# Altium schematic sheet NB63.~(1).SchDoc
size 279 x 215 mm
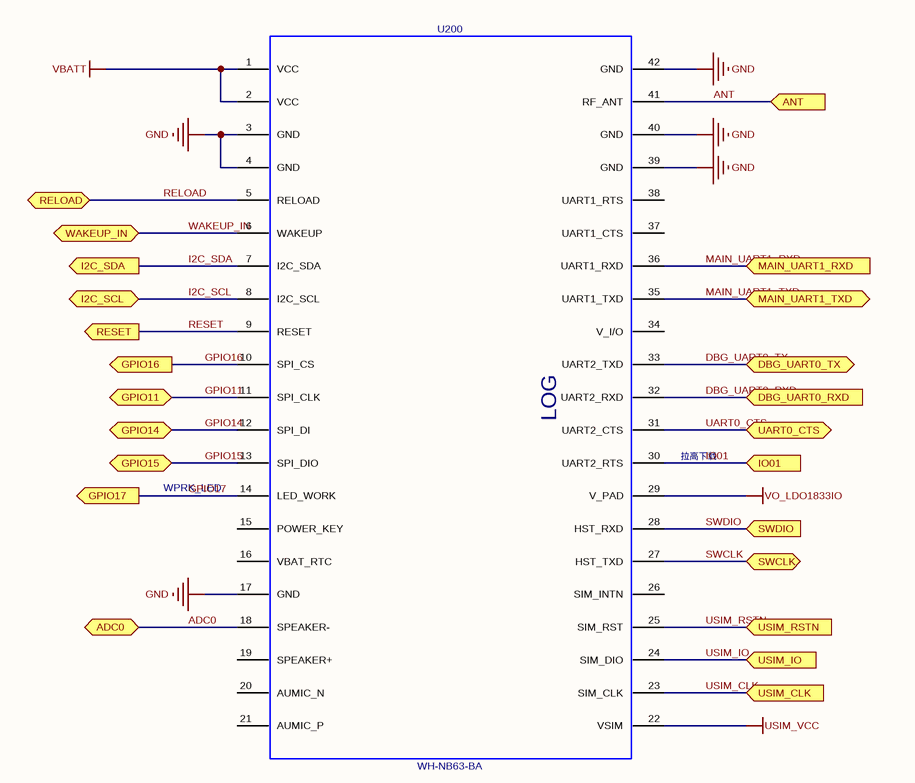
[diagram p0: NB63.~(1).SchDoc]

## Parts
U200  WH-NB63-BA  [NB63-I/O]

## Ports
ADC0 (bidir), ANT, DBG_UART0_RXD (in), DBG_UART0_TX (bidir), GPIO11 (bidir), GPIO14 (bidir), GPIO15 (bidir), GPIO16 (out), GPIO17 (out), I2C_SCL (bidir), I2C_SDA (out), IO01 (in), MAIN_UART1_RXD (in), MAIN_UART1_TXD (bidir), RELOAD (bidir), RESET (out), SWCLK (bidir), SWDIO (in), UART0_CTS (bidir), USIM_CLK (in), USIM_IO (in), USIM_RSTN (in), WAKEUP_IN (bidir)

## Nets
GND: U200.3(GND) U200.4(GND) U200.17(GND) U200.39(GND) U200.40(GND) U200.42(GND)
USIM_VCC: U200.22(VSIM)
VBATT: U200.1(VCC) U200.2(VCC)
VO_LDO1833IO: U200.29(V_PAD)
ADC0: U200.18(SPEAKER-) ; port ADC0
ANT: U200.41(RF_ANT) ; port ANT
DBG_UART0_RXD: U200.32(UART2_RXD) ; port DBG_UART0_RXD
DBG_UART0_TX: U200.33(UART2_TXD) ; port DBG_UART0_TX
GPIO11: U200.11(SPI_CLK) ; port GPIO11
GPIO14: U200.12(SPI_DI) ; port GPIO14
GPIO15: U200.13(SPI_DIO) ; port GPIO15
GPIO16: U200.10(SPI_CS) ; port GPIO16
GPIO17: U200.14(LED_WORK) ; port GPIO17
I2C_SCL: U200.8(I2C_SCL) ; port I2C_SCL
I2C_SDA: U200.7(I2C_SDA) ; port I2C_SDA
IO01: U200.30(UART2_RTS) ; port IO01
MAIN_UART1_RXD: U200.36(UART1_RXD) ; port MAIN_UART1_RXD
MAIN_UART1_TXD: U200.35(UART1_TXD) ; port MAIN_UART1_TXD
RELOAD: U200.5(RELOAD) ; port RELOAD
RESET: U200.9(RESET) ; port RESET
SWCLK: U200.27(HST_TXD) ; port SWCLK
SWDIO: U200.28(HST_RXD) ; port SWDIO
UART0_CTS: U200.31(UART2_CTS) ; port UART0_CTS
USIM_CLK: U200.23(SIM_CLK) ; port USIM_CLK
USIM_IO: U200.24(SIM_DIO) ; port USIM_IO
USIM_RSTN: U200.25(SIM_RST) ; port USIM_RSTN
WAKEUP_IN: U200.6(WAKEUP) ; port WAKEUP_IN

Not connected (* = marked no-connect by the designer): U200 15(POWER_KEY) 16(VBAT_RTC) 19(SPEAKER+) 20(AUMIC_N) 21(AUMIC_P) 26(SIM_INTN) 34(V_I/O) 37(UART1_CTS) 38(UART1_RTS)

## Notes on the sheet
- (near U200) LOG
- (near U200) WPRK_LED
- (near U200) 拉高下载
